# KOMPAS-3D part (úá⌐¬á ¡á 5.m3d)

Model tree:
1. Эскиз:1
2. Операция выдавливания:1
     Расстояние 1 = 2
3. Эскиз:4
4. Отверстие:2
5. Условное изображение резьбы:2
     Длина резьбы = 2; Шаг резьбы = 1.5; Номинальный диаметр резьбы = 6.6238
6. Скругление:2
     Радиус = 0.1

Referenced files in C:\Program Files\ASCON\KOMPAS-3D V13 Home\Sys\: holelib.lfr
Referenced files in C:\Program Files\ASCON\KOMPAS-3D V12\Sys\: holelib.lfr
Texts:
  гайка на 5
  Отверстие 01
  (вариант 1)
